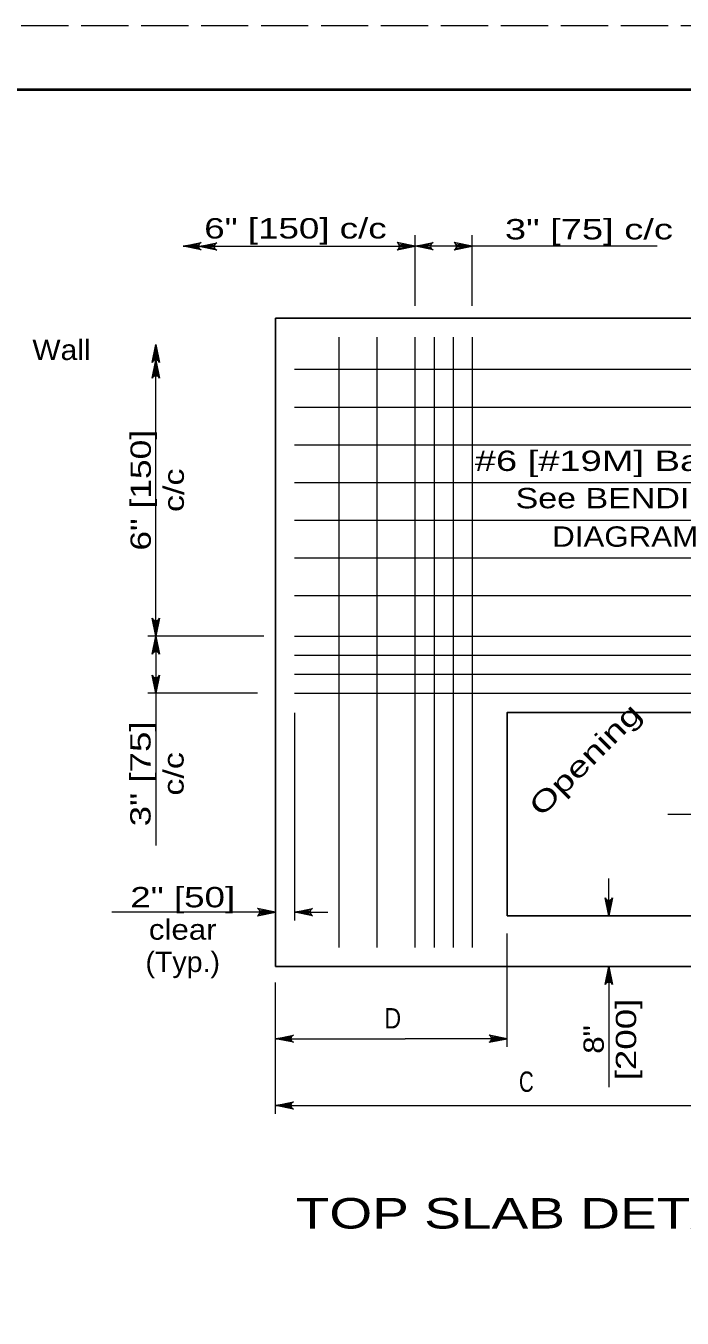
# Model space of a CAD drawing. Extents: x 1073.4 to 1107.4, y 719.4 to 741.4.
# Drawn here: x 1090.03 to 1095.2, y 731.19 to 741.35 of the extents above; entities that cross this region are included whole.
import ezdxf
from ezdxf.enums import TextEntityAlignment as Align

# ---------------------------------------------------------------- set-up
doc = ezdxf.new("R2010")
doc.units = 0
doc.header["$LTSCALE"] = 0.062
doc.linetypes.add('LONG_DASHED', pattern=[7.5, 6, -1.5])
doc.layers.add('1', color=7, linetype='Continuous', lineweight=13)

msp = doc.modelspace()

# ---------------------------------------------------------------- linework, layer by layer
at = {"layer": '1', "lineweight": 25}
for p, q in [((1075.36142, 740.85408), (1106.86142, 740.85408)), ((1091.99858, 739.05525), (1091.99858, 733.95817)), ((1091.99858, 733.95817), (1095.82183, 733.95817))]:
    msp.add_line(p, q, dxfattribs=at)
at = {"layer": '1'}
for p, q in [((1091.40017, 739.63917), (1091.272, 739.62125)), ((1091.39583, 739.63033), (1091.272, 739.62125)), ((1091.272, 739.62125), (1093.09717, 739.62125)), ((1091.3945, 739.62125), (1091.272, 739.62125)), ((1091.39683, 739.60975), (1091.272, 739.62125)), ((1091.40167, 739.6015), (1091.272, 739.62125)), ((1091.5235, 739.63683), (1091.39533, 739.61892)), ((1091.51917, 739.628), (1091.39533, 739.61892)), ((1091.51783, 739.61892), (1091.39533, 739.61892)), ((1091.52017, 739.60742), (1091.39533, 739.61892)), ((1091.52508, 739.59908), (1091.39533, 739.61892)), ((1092.9675, 739.6015), (1093.09717, 739.62125)), ((1092.969, 739.63917), (1093.09717, 739.62125)), ((1092.97242, 739.60975), (1093.09717, 739.62125)), ((1092.97333, 739.63033), (1093.09717, 739.62125)), ((1092.97467, 739.62125), (1093.09717, 739.62125)), ((1093.09717, 739.15392), (1093.09717, 739.70767)), ((1093.22542, 739.63917), (1093.09717, 739.62125)), ((1093.22108, 739.63033), (1093.09717, 739.62125)), ((1095.00192, 739.62125), (1093.09717, 739.62125)), ((1093.21975, 739.62125), (1093.09717, 739.62125)), ((1093.222, 739.60975), (1093.09717, 739.62125)), ((1093.22692, 739.6015), (1093.09717, 739.62125)), ((1093.41725, 739.6015), (1093.547, 739.62125)), ((1093.41883, 739.63917), (1093.547, 739.62125)), ((1093.42217, 739.60975), (1093.547, 739.62125)), ((1093.42317, 739.63033), (1093.547, 739.62125)), ((1093.4245, 739.62125), (1093.547, 739.62125)), ((1093.547, 739.15392), (1093.547, 739.70767)), ((1091.03783, 738.71967), (1091.05758, 738.84933)), ((1091.04617, 738.7245), (1091.05758, 738.84933)), ((1091.05758, 736.5565), (1091.05758, 738.84933)), ((1091.05758, 738.72683), (1091.05758, 738.84933)), ((1091.06667, 738.7255), (1091.05758, 738.84933)), ((1091.0755, 738.72117), (1091.05758, 738.84933)), ((1091.05758, 736.5565), (1091.05758, 738.84933)), ((1092.4995, 734.10808), (1092.4995, 738.90533)), ((1092.79942, 734.10808), (1092.79942, 738.90533)), ((1093.09717, 734.10808), (1093.09717, 738.90533)), ((1093.24917, 734.10808), (1093.24917, 738.90533)), ((1093.39917, 734.10808), (1093.39917, 738.90533)), ((1093.54908, 734.10808), (1093.54908, 738.90533)), ((1091.03783, 738.59533), (1091.05758, 738.72508)), ((1091.04617, 738.60025), (1091.05758, 738.72508)), ((1091.05758, 738.6025), (1091.05758, 738.72508)), ((1091.06667, 738.60117), (1091.05758, 738.72508)), ((1091.0755, 738.59683), (1091.05758, 738.72508)), ((1092.1485, 738.65533), (1095.67183, 738.65533)), ((1092.1485, 738.3555), (1095.67183, 738.3555)), ((1092.1485, 738.05958), (1095.67183, 738.05958)), ((1092.1485, 737.76375), (1095.67183, 737.76375)), ((1092.1485, 737.46783), (1095.67183, 737.46783)), ((1092.1485, 737.17192), (1095.67183, 737.17192)), ((1092.1485, 736.87608), (1095.67183, 736.87608)), ((1091.03967, 736.68475), (1091.05758, 736.5565)), ((1091.0485, 736.68042), (1091.05758, 736.5565)), ((1091.0775, 736.68625), (1091.05758, 736.5565)), ((1091.06917, 736.68133), (1091.05758, 736.5565)), ((1091.05758, 736.67908), (1091.05758, 736.5565)), ((1091.90708, 736.5565), (1090.99467, 736.5565)), ((1091.85858, 736.5565), (1090.99467, 736.5565)), ((1091.03783, 736.42683), (1091.05758, 736.5565)), ((1091.04617, 736.43175), (1091.05758, 736.5565)), ((1091.05758, 736.434), (1091.05758, 736.5565)), ((1091.06667, 736.43267), (1091.05758, 736.5565)), ((1091.0755, 736.42833), (1091.05758, 736.5565)), ((1091.05758, 736.5565), (1091.05758, 734.90942)), ((1092.1485, 736.5565), (1095.67183, 736.5565)), ((1092.1485, 736.40667), (1095.67183, 736.40667)), ((1091.03967, 736.235), (1091.05758, 736.10683)), ((1091.0485, 736.23067), (1091.05758, 736.10683)), ((1091.0775, 736.2365), (1091.05758, 736.10683)), ((1091.06917, 736.23158), (1091.05758, 736.10683)), ((1091.05758, 736.22933), (1091.05758, 736.10683)), ((1092.1485, 736.25675), (1095.67183, 736.25675)), ((1091.85858, 736.10683), (1090.99467, 736.10683)), ((1092.1485, 736.10683), (1095.67183, 736.10683)), ((1092.1485, 735.95217), (1092.1485, 734.31958)), ((1095.08658, 735.1575), (1095.422, 735.1575)), ((1094.62233, 734.35792), (1094.62233, 734.64983)), ((1094.60442, 734.48617), (1094.62233, 734.35792)), ((1094.61325, 734.48183), (1094.62233, 734.35792)), ((1094.64217, 734.48767), (1094.62233, 734.35792)), ((1094.63383, 734.48275), (1094.62233, 734.35792)), ((1094.62233, 734.4805), (1094.62233, 734.35792)), ((1091.99858, 734.38625), (1090.71217, 734.38625)), ((1091.86883, 734.36642), (1091.99858, 734.38625)), ((1091.87042, 734.40417), (1091.99858, 734.38625)), ((1091.87383, 734.37475), (1091.99858, 734.38625)), ((1091.87475, 734.39533), (1091.99858, 734.38625)), ((1091.87608, 734.38625), (1091.99858, 734.38625)), ((1092.27675, 734.40417), (1092.1485, 734.38625)), ((1092.27242, 734.39533), (1092.1485, 734.38625)), ((1092.1485, 734.38625), (1092.41058, 734.38625)), ((1092.27108, 734.38625), (1092.1485, 734.38625)), ((1092.27333, 734.37475), (1092.1485, 734.38625)), ((1092.27817, 734.36642), (1092.1485, 734.38625)), ((1093.82275, 733.32858), (1093.82275, 734.21917)), ((1094.6025, 733.8285), (1094.62233, 733.95817)), ((1094.61083, 733.83342), (1094.62233, 733.95817)), ((1094.62233, 733.83567), (1094.62233, 733.95817)), ((1094.63142, 733.83433), (1094.62233, 733.95817)), ((1094.64025, 733.83), (1094.62233, 733.95817)), ((1094.62233, 733.95817), (1094.62233, 733.00983)), ((1091.99858, 732.80033), (1091.99858, 733.83267)), ((1092.12683, 733.4095), (1091.99858, 733.3915)), ((1092.1225, 733.40058), (1091.99858, 733.3915)), ((1091.99858, 733.3915), (1093.01867, 733.39142)), ((1092.12117, 733.3915), (1091.99858, 733.3915)), ((1092.12342, 733.38), (1091.99858, 733.3915)), ((1092.12833, 733.37167), (1091.99858, 733.3915)), ((1091.99858, 733.3915), (1093.01867, 733.39142)), ((1093.82275, 733.3915), (1093.01867, 733.3915)), ((1093.69308, 733.37167), (1093.82275, 733.3915)), ((1093.69458, 733.4095), (1093.82275, 733.3915)), ((1093.69792, 733.38), (1093.82275, 733.3915)), ((1093.69892, 733.40058), (1093.82275, 733.3915)), ((1093.70017, 733.3915), (1093.82275, 733.3915)), ((1092.12683, 732.88492), (1091.99858, 732.867)), ((1092.1225, 732.87608), (1091.99858, 732.867)), ((1092.12117, 732.867), (1091.99858, 732.867)), ((1092.12342, 732.8555), (1091.99858, 732.867)), ((1092.12833, 732.84717), (1091.99858, 732.867)), ((1091.99858, 732.867), (1095.82183, 732.867))]:
    msp.add_line(p, q, dxfattribs=at)
at = {"layer": '1', "linetype": 'LONG_DASHED'}
msp.add_lwpolyline([(1073.36142, 719.35408), (1107.36142, 719.35408), (1107.36142, 741.35408), (1073.36142, 741.35408)], close=True, dxfattribs=at)
at = {"layer": '1', "lineweight": 40}
msp.add_lwpolyline([(1075.36142, 740.85408), (1106.86142, 740.85408), (1106.86142, 719.85408), (1075.36142, 719.85408)], close=True, dxfattribs=at)
msp.add_lwpolyline([(1075.36142, 740.85408), (1106.86142, 740.85408), (1106.86142, 719.85408), (1075.36142, 719.85408)], close=True, dxfattribs=at)
at = {"layer": '1'}
for points in [[(1091.41358, 739.59292), (1091.272, 739.62125), (1091.41358, 739.64958)], [(1091.53692, 739.59058), (1091.39533, 739.61892), (1091.53692, 739.64725)], [(1092.95558, 739.59292), (1093.09717, 739.62125), (1092.95558, 739.64958)], [(1093.23883, 739.59292), (1093.09717, 739.62125), (1093.23883, 739.64958)], [(1093.40542, 739.59292), (1093.547, 739.62125), (1093.40542, 739.64958)], [(1091.02925, 738.70775), (1091.05758, 738.84933), (1091.08592, 738.70775)], [(1091.02925, 738.5835), (1091.05758, 738.72508), (1091.08592, 738.5835)], [(1091.08592, 736.69817), (1091.05758, 736.5565), (1091.02925, 736.69817)], [(1091.02925, 736.41492), (1091.05758, 736.5565), (1091.08592, 736.41492)], [(1091.08592, 736.24842), (1091.05758, 736.10683), (1091.02925, 736.24842)], [(1094.65067, 734.4995), (1094.62233, 734.35792), (1094.594, 734.4995)], [(1091.857, 734.35792), (1091.99858, 734.38625), (1091.857, 734.4145)], [(1092.29017, 734.35792), (1092.1485, 734.38625), (1092.29017, 734.4145)], [(1094.594, 733.81658), (1094.62233, 733.95817), (1094.65067, 733.81658)], [(1092.14017, 733.36317), (1091.99858, 733.3915), (1092.14017, 733.41983)], [(1093.68117, 733.36317), (1093.82275, 733.3915), (1093.68117, 733.41983)], [(1092.14017, 732.83867), (1091.99858, 732.867), (1092.14017, 732.89525)]]:
    msp.add_lwpolyline(points, dxfattribs=at)
at = {"layer": '1', "lineweight": 25}
msp.add_lwpolyline([(1091.99858, 739.05525), (1095.82183, 739.05525), (1095.82183, 733.95817)], dxfattribs=at)
msp.add_lwpolyline([(1095.422, 734.35792), (1095.422, 735.957), (1093.82275, 735.957), (1093.82275, 734.35792)], close=True, dxfattribs=at)
at = {"layer": '1'}
for centre, start, end in [((1091.42502, 739.62131), 112.08782, 247.91395), ((1091.54836, 739.61895), 112.08782, 247.91395), ((1092.94417, 739.62131), 292.08605, 67.91218), ((1093.25024, 739.62131), 112.08782, 247.91395), ((1093.39396, 739.62131), 292.08605, 67.91218), ((1091.05765, 738.69633), 22.08782, 157.91395), ((1091.05765, 738.572), 22.08782, 157.91395), ((1091.05759, 736.70958), 202.08782, 337.91395), ((1091.05765, 736.40351), 22.08782, 157.91395), ((1091.05759, 736.25984), 202.08782, 337.91395), ((1094.62232, 734.51098), 202.08782, 337.91395), ((1091.84555, 734.38628), 292.08605, 67.91218), ((1092.30155, 734.38628), 112.08782, 247.91395), ((1094.62238, 733.80514), 22.08782, 157.91395), ((1092.15166, 733.39154), 112.08782, 247.91395), ((1093.66973, 733.39154), 292.08605, 67.91218), ((1092.15166, 732.867), 112.08782, 247.91395)]:
    msp.add_arc(centre, 0.03056, start, end, dxfattribs=at)

# ---------------------------------------------------------------- texts
for s, width, p in [('6" [150] c/c', 1.35, (1092.15604, 739.68225)), ('3" [75] c/c', 1.4, (1094.46567, 739.67517)), ('2" [50]', 1.35, (1091.26921, 734.42417)), ('clear', 1.15, (1091.26929, 734.16975)), ('(Typ.)', 1.05, (1091.26925, 733.91533))]:
    msp.add_text(s, height=0.16, dxfattribs=dict(at, width=width)).set_placement(p, align=Align.CENTER)
for s, height, width, p in [('Wall', 0.16, 1.1, (1090.08592, 738.72708)), ('#6 [#19M] Bars', 0.16, 1.4, (1093.5675, 737.85483)), ('See BENDING', 0.16, 1.25, (1093.88842, 737.56125)), ('DIAGRAM', 0.16, 1.15, (1094.17675, 737.259)), ('D', 0.16, 0.85, (1092.8565, 733.47208)), ('C', 0.16, 0.75, (1093.91533, 732.9735)), ('TOP SLAB DETAIL', 0.24, 1.35, (1092.15842, 731.89892))]:
    msp.add_text(s, height=height, dxfattribs=dict(at, width=width)).set_placement(p)
for s, width, p in [('6" [150]', 1.3, (1091.01833, 737.70308)), ('c/c', 1.25, (1091.27833, 737.70308)), ('3" [75]', 1.35, (1091.01617, 735.47362)), ('c/c', 1.25, (1091.27617, 735.47358)), ('[200]', 1.35, (1094.83725, 733.38529)), ('8"', 1.15, (1094.58283, 733.38521))]:
    msp.add_text(s, height=0.16, rotation=90, dxfattribs=dict(at, width=width)).set_placement(p, align=Align.CENTER)
at = {"layer": '1', "width": 1.4}
msp.add_text('Opening', height=0.16, rotation=44.997, dxfattribs=at).set_placement((1094.09175, 735.12875))

doc.saveas('drawing.dxf')
